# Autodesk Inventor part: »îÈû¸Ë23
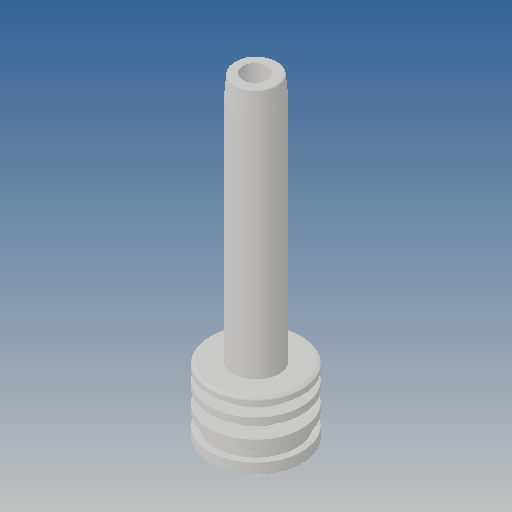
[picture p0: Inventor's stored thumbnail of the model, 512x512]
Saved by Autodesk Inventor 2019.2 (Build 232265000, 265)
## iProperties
Created: 2013-09
Part Number: »îÈû¸Ë23
Material: Ogólny
Document SubType Name: Modeling
Designer: CADENGINEERING4
Density: 1 g/cm^3
Appearance: Domyślna
Author: CADENGINEERING4
Revision Number: ÈÎºÎ
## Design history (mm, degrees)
feature "_12.0 (12) Ö±¾¶¿×1"
node "Bryła1"
